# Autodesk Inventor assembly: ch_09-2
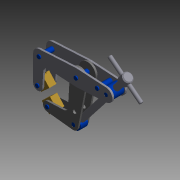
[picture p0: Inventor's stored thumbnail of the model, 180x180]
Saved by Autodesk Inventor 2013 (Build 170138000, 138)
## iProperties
Shininess: 0.0
Length Units: 11272
Angle Units: 11279
Time Units: 11290
Mass Units: 11286
Length Display Precision: 3
Angle Display Precision: 2
Compacted: True
Created: 2000-02
Part Number: ch_09-2
Document SubType Name: Assembly
Designer: Administrator
Mass: 621.139 g
Surface Area: 498.588 cm^2
Volume: 76.8451 cm^3
Density: 8.08301 g/cm^3
Density: 0.0
Volumn: 0.0
Area: 0.0
PropertySet Name: Model Information
Control State: 0
Checked Out: False
Master: False
Author: Administrator
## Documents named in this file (11)
- C:\Users\boganb\Documents\B2 Design\Goodyear\2013 Tutorial Files\Assembly FEA 1\analyze-2.iam
- C:\Users\boganb\Documents\B2 Design\Goodyear\2013 Tutorial Files\Assembly FEA 1\Upper_Plate.ipt
- C:\Users\boganb\Documents\B2 Design\Goodyear\2013 Tutorial Files\Assembly FEA 1\Lower_Plate.ipt
- C:\Users\boganb\Documents\B2 Design\Goodyear\2013 Tutorial Files\Assembly FEA 1\Pivot_Threaded.ipt
- C:\Users\boganb\Documents\B2 Design\Goodyear\2013 Tutorial Files\Assembly FEA 1\Pivot_Lower.ipt
- C:\Users\boganb\Documents\B2 Design\Goodyear\2013 Tutorial Files\Assembly FEA 1\Screw.ipt
- C:\Users\boganb\Documents\B2 Design\Goodyear\2013 Tutorial Files\Assembly FEA 1\Pin_A.ipt
- C:\Users\boganb\Documents\B2 Design\Goodyear\2013 Tutorial Files\Assembly FEA 1\Pin_B.ipt
- C:\Users\boganb\Documents\B2 Design\Goodyear\2013 Tutorial Files\Assembly FEA 1\Handle.ipt
- C:\Users\boganb\Documents\B2 Design\Goodyear\2013 Tutorial Files\Assembly FEA 1\SHCS_10-32x6.ipt
- C:\Users\boganb\Documents\B2 Design\Goodyear\2013 Tutorial Files\Assembly FEA 1\Grip.ipt
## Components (16 placed, 11 different names)
1. Upper_Plate:1 — Flush:1, Mate:1, Mate:2, Mate:6
2. Upper_Plate:2 — Mate:1, Mate:3, Mate:4, Mate:7, Mate:10, Mate:11, Mate:12, Mate:13, Mate:14, Mate:15, Mate:16, Mate:17
3. Lower_Plate:1 — Mate:2, Mate:5
4. Lower_Plate:2 — Mate:3, Mate:4, Mate:5, Mate:8, Mate:18, Mate:19
5. Pin_A:1 — Mate:10, Mate:14, Mate:24
6. Pin_A:2 — Mate:11, Mate:15
7. Pin_A:3 — Mate:12, Mate:16
8. Pin_A:4 — Mate:13, Mate:17
9. Pin_B:1 — Mate:18, Mate:19, Mate:26
10. Pivot_Threaded:1 — Mate:6, Mate:7, Mate:9
11. Handle:1 — Mate:20, Mate:21, Mate:22
12. Screw:1 — Mate:9, Mate:20, Mate:21, Mate:22, Mate:23, Insert:1, Insert:2
13. Pivot_Lower:1 — Mate:8, Insert:1
14. SHCS_10-32x6:1 — Insert:2
15. ch_09-Upper_Grip.ipt:1 — Mate:24, Mate:25, Mate:27, Angle:1
16. ch_09-Lower_Grip.ipt:1 — Mate:26, Mate:27, Angle:1
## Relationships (31: Mate 27, Insert 2, Flush 1, Angle 1)
- Flush:1: Upper_Plate:1
- Mate:1: Upper_Plate:1 ↔ Upper_Plate:2
- Mate:2: Upper_Plate:1 ↔ Lower_Plate:1
- Mate:3: Upper_Plate:2 ↔ Lower_Plate:2
- Mate:4: Upper_Plate:2 ↔ Lower_Plate:2
- Mate:5: Lower_Plate:1 ↔ Lower_Plate:2
- Mate:6: Upper_Plate:1 ↔ Pivot_Threaded:1
- Mate:7: Upper_Plate:2 ↔ Pivot_Threaded:1
- Mate:8: Lower_Plate:2 ↔ Pivot_Lower:1
- Mate:9: Pivot_Threaded:1 ↔ Screw:1
- Mate:10: Upper_Plate:2 ↔ Pin_A:1
- Mate:11: Upper_Plate:2 ↔ Pin_A:2
- Mate:12: Upper_Plate:2 ↔ Pin_A:3
- Mate:13: Upper_Plate:2 ↔ Pin_A:4
- Mate:14: Upper_Plate:2 ↔ Pin_A:1
- Mate:15: Upper_Plate:2 ↔ Pin_A:2
- Mate:16: Upper_Plate:2 ↔ Pin_A:3
- Mate:17: Upper_Plate:2 ↔ Pin_A:4
- Mate:18: Lower_Plate:2 ↔ Pin_B:1
- Mate:19: Lower_Plate:2 ↔ Pin_B:1
- Mate:20: Handle:1 ↔ Screw:1
- Mate:21: Handle:1 ↔ Screw:1
- Mate:22: Handle:1 ↔ Screw:1
- Mate:23: Screw:1
- Insert:1: Screw:1 ↔ Pivot_Lower:1
- Insert:2: Screw:1 ↔ SHCS_10-32x6:1
- Mate:24: Pin_A:1 ↔ ch_09-Upper_Grip.ipt:1
- Mate:25: ch_09-Upper_Grip.ipt:1
- Mate:26: Pin_B:1 ↔ ch_09-Lower_Grip.ipt:1
- Mate:27: ch_09-Upper_Grip.ipt:1 ↔ ch_09-Lower_Grip.ipt:1
- Angle:1: ch_09-Upper_Grip.ipt:1 ↔ ch_09-Lower_Grip.ipt:1
